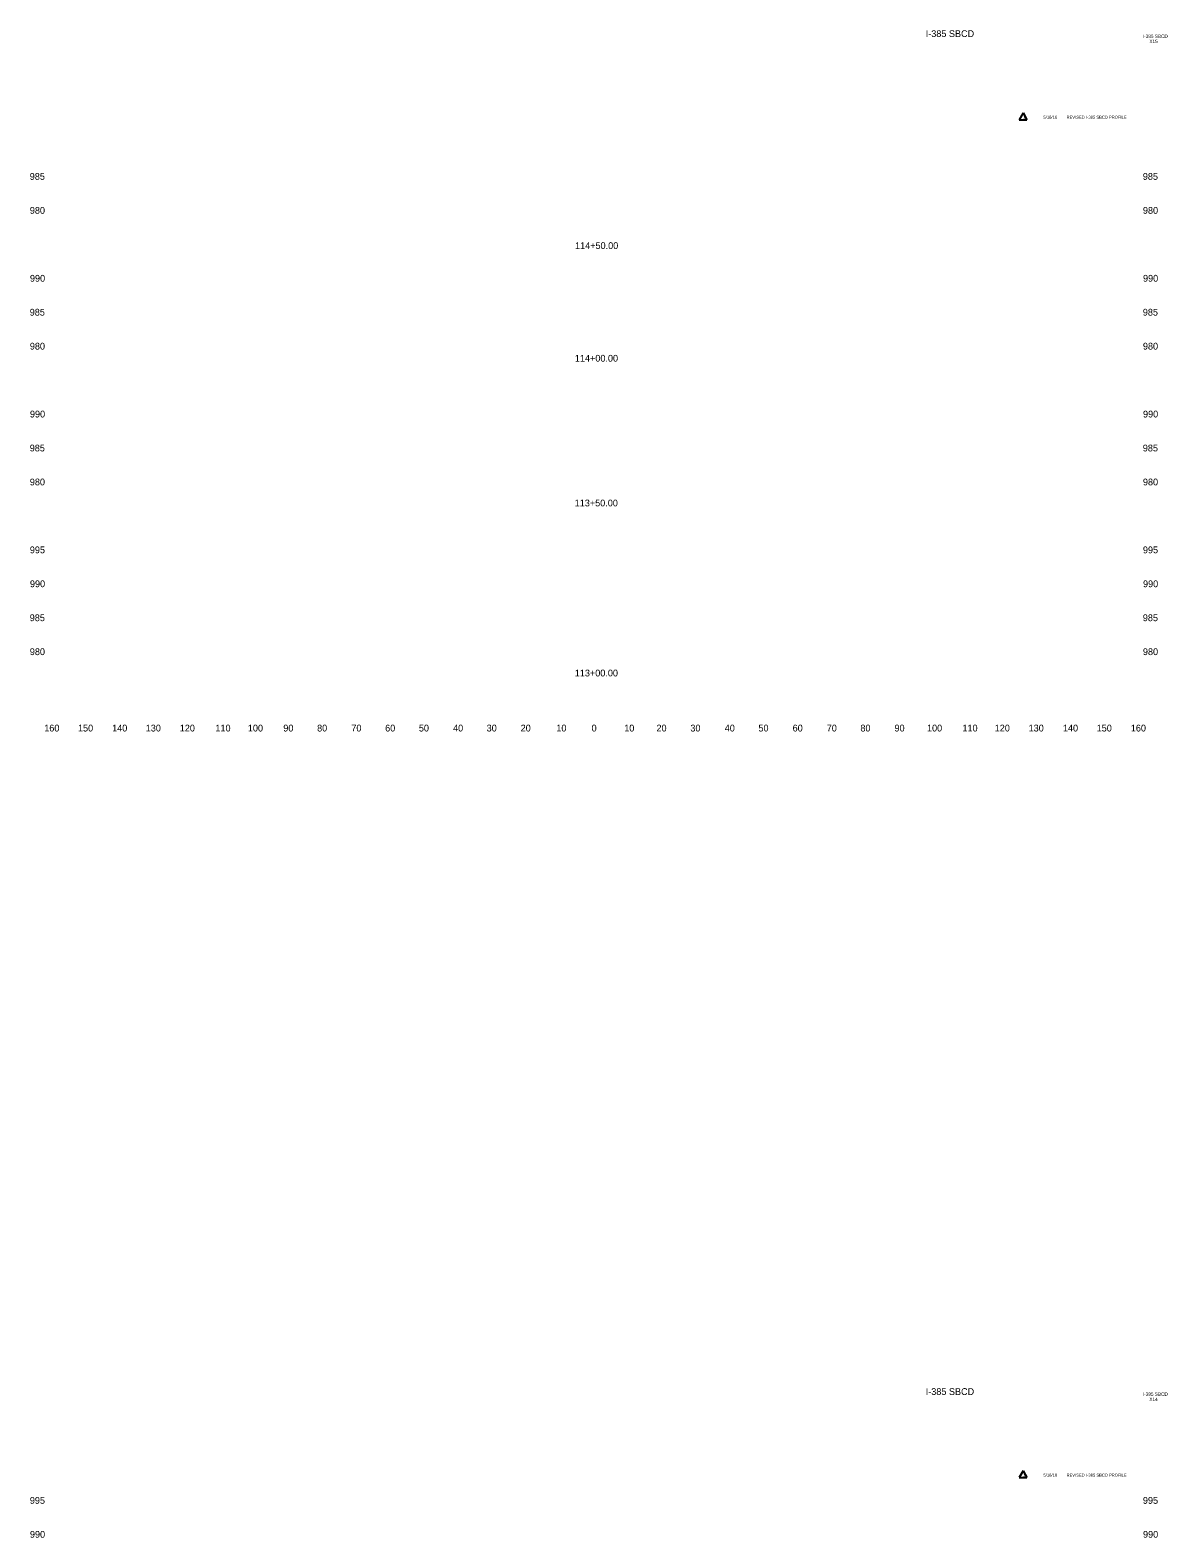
# Model space of a CAD drawing. Extents: x 4994 to 6876, y 4997 to 8804.
# Drawn here: x 5509 to 5843.7, y 6360 to 6804.1 of the extents above; entities that cross this region are included whole.
import ezdxf

# ---------------------------------------------------------------- set-up
doc = ezdxf.new("R2010")
doc.units = 0
for name, color, linetype in [('RD_SHT_ID', 7, 'Continuous'), ('RD_SHT_TX', 7, 'Continuous'), ('RD_XS_TX_Offset', 7, 'Continuous'), ('RD_XS_TX_Station', 7, 'Continuous')]:
    doc.layers.add(name, color=color, linetype=linetype)

msp = doc.modelspace()

# ---------------------------------------------------------------- linework, layer by layer
at = {"layer": 'RD_SHT_TX'}
for p, q in [((5801.37, 6779.75), (5800.23, 6777.72)), ((5800.23, 6777.72), (5802.51, 6777.72)), ((5801.37, 6779.75), (5802.51, 6777.72)), ((5801.37, 6379.75), (5800.23, 6377.72)), ((5800.23, 6377.72), (5802.51, 6377.72)), ((5801.37, 6379.75), (5802.51, 6377.72))]:
    msp.add_line(p, q, dxfattribs=at)

# ---------------------------------------------------------------- texts
at = {"layer": 'RD_SHT_ID'}
for s, height, p in [('I-385 SBCD', 2, (5772.69, 6802.06)), ('I-385 SBCD', 1, (5836.63, 6801.8)), ('X15', 1, (5838.57, 6800.3)), ('I-385 SBCD', 2, (5772.69, 6402.06)), ('I-385 SBCD', 1, (5836.63, 6401.8)), ('X14', 1, (5838.57, 6400.3))]:
    msp.add_text(s, height=height, dxfattribs=at).set_placement(p)
at = {"layer": 'RD_SHT_TX'}
for s, p in [('1', (5801.37, 6778.05)), ('5/16/16', (5807.34, 6778.01)), ('REVISED I-385 SBCD PROFILE', (5814.17, 6778.01)), ('1', (5801.37, 6378.05)), ('5/16/16', (5807.34, 6378.01)), ('REVISED I-385 SBCD PROFILE', (5814.17, 6378.01))]:
    msp.add_text(s, height=0.88, dxfattribs=at).set_placement(p)
at = {"layer": 'RD_XS_TX_Offset'}
for s, p in [('985', (5508.83, 6760)), ('985', (5836.63, 6760)), ('980', (5508.86, 6750)), ('980', (5836.66, 6750)), ('990', (5508.89, 6730)), ('990', (5836.69, 6730)), ('985', (5508.83, 6720)), ('985', (5836.63, 6720)), ('980', (5508.86, 6710)), ('980', (5836.66, 6710)), ('990', (5508.89, 6690)), ('990', (5836.69, 6690)), ('985', (5508.83, 6680)), ('985', (5836.63, 6680)), ('980', (5508.86, 6670)), ('980', (5836.66, 6670)), ('995', (5508.86, 6650)), ('995', (5836.66, 6650)), ('990', (5508.89, 6640)), ('990', (5836.69, 6640)), ('985', (5508.83, 6630)), ('985', (5836.63, 6630)), ('980', (5508.86, 6620)), ('980', (5836.66, 6620)), ('160', (5513.1, 6597.5)), ('150', (5523.04, 6597.5)), ('140', (5533.1, 6597.5)), ('130', (5542.99, 6597.5)), ('120', (5553.01, 6597.5)), ('110', (5563.51, 6597.5)), ('100', (5573.07, 6597.5)), ('90', (5583.5, 6597.5)), ('80', (5593.46, 6597.5)), ('70', (5603.54, 6597.5)), ('60', (5613.5, 6597.5)), ('50', (5623.43, 6597.5)), ('40', (5633.5, 6597.5)), ('30', (5643.39, 6597.5)), ('20', (5653.4, 6597.5)), ('10', (5663.91, 6597.5)), ('0', (5674.3, 6597.5)), ('0', (5674.3, 6597.5)), ('10', (5683.91, 6597.5)), ('20', (5693.4, 6597.5)), ('30', (5703.39, 6597.5)), ('40', (5713.5, 6597.5)), ('50', (5723.43, 6597.5)), ('60', (5733.5, 6597.5)), ('70', (5743.54, 6597.5)), ('80', (5753.46, 6597.5)), ('90', (5763.5, 6597.5)), ('100', (5773.07, 6597.5)), ('110', (5783.51, 6597.5)), ('120', (5793.01, 6597.5)), ('130', (5802.99, 6597.5)), ('140', (5813.1, 6597.5)), ('150', (5823.04, 6597.5)), ('160', (5833.1, 6597.5)), ('995', (5508.86, 6370)), ('995', (5836.66, 6370)), ('990', (5508.89, 6360)), ('990', (5836.69, 6360))]:
    msp.add_text(s, height=2, dxfattribs=at).set_placement(p)
at = {"layer": 'RD_XS_TX_Station'}
for s, p in [('114+50.00', (5669.43, 6739.63)), ('114+00.00', (5669.37, 6706.44)), ('113+50.00', (5669.32, 6663.81)), ('113+00.00', (5669.35, 6613.72))]:
    msp.add_text(s, height=2, dxfattribs=at).set_placement(p)

doc.saveas('drawing.dxf')
